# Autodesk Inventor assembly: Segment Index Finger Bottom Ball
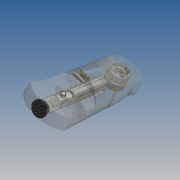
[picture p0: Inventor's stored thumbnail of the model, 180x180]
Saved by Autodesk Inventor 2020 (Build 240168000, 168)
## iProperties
Created: 2019-10
Part Number: Segment Index Finger Bottom Ball
Document SubType Name: Assembly
Designer: yello
Author: yello
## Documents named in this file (8)
- C:\Users\yello\Documents\Mechanical Hand\Prototype 2 (Realistic Hand)\Segment Index Finger Bottom Ball.iam
- C:\Users\yello\Documents\Mechanical Hand\Prototype 2 (Realistic Hand)\Segment Index Finger Bottom.ipt
- C:\Users\yello\Documents\Mechanical Hand\Prototype 2 (Realistic Hand)\Push Part.ipt
- C:\Users\yello\Documents\Mechanical Hand\Prototype 2 (Realistic Hand)\Plug.ipt
- C:\Users\yello\Documents\Mechanical Hand\Prototype 2 (Realistic Hand)\Spring.ipt
- C:\Users\yello\Documents\Mechanical Hand\Prototype 2 (Realistic Hand)\Ball.ipt
- C:\Users\yello\Documents\Mechanical Hand\Prototype 2 (Realistic Hand)\Lock.ipt
- C:\Users\yello\Documents\Mechanical Hand\Prototype 2 (Realistic Hand)\Bearings.iam
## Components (8 placed, 7 different names)
1. Segment Index Finger Bottom:1 — Mate:1, Mate:2, Mate:3, Mate:5, Mate:6, Mate:7, Mate:10, Mate:11, Flush:1
2. Push Part:1 — Mate:1, Mate:8, Mate:9
3. Plug:1 — Mate:2, Mate:3
4. Spring:1 — Mate:5
5. Ball:1 — Mate:6
6. Ball:2 — Mate:7
7. Lock:1 — Mate:8, Mate:9, Mate:10
8. Bearings:1 [sub-assembly] — Mate:11, Flush:1
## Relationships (11: Mate 10, Flush 1)
- Mate:1: Segment Index Finger Bottom:1 ↔ Push Part:1
- Mate:2: Segment Index Finger Bottom:1 ↔ Plug:1
- Mate:3: Segment Index Finger Bottom:1 ↔ Plug:1
- Mate:5: Segment Index Finger Bottom:1 ↔ Spring:1
- Mate:6: Segment Index Finger Bottom:1 ↔ Ball:1
- Mate:7: Segment Index Finger Bottom:1 ↔ Ball:2
- Mate:8: Push Part:1 ↔ Lock:1
- Mate:9: Push Part:1 ↔ Lock:1
- Mate:10: Segment Index Finger Bottom:1 ↔ Lock:1
- Mate:11: Segment Index Finger Bottom:1 ↔ Bearings:1
- Flush:1: Segment Index Finger Bottom:1 ↔ Bearings:1
